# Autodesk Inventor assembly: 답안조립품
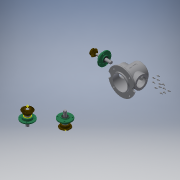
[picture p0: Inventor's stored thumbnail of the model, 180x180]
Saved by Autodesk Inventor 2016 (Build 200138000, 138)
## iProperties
Created: 2018-04
Part Number: 답안조립품
Material: 일반
Document SubType Name: Assembly
Designer: 605-06
Author: 605-06
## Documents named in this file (16)
- C:\Users\605-06\Desktop\480407V1010\답안조립품.iam
- C:\Users\605-06\Desktop\480407V1010\메인 베벨기어.ipt
- C:\Users\605-06\Desktop\480407V1010\메인 축.ipt
- 메인 축.ipt
- C:\Users\605-06\Desktop\480407V1010\베어링 6203.ipt
- C:\Users\605-06\Desktop\480407V1010\본체.ipt
- C:\Users\605-06\Desktop\480407V1010\볼트 M4.ipt
- 볼트 M4.ipt
- C:\Users\605-06\Desktop\480407V1010\서브 베벨기어.ipt
- C:\Users\605-06\Desktop\480407V1010\서브 축.ipt
- 서브 축.ipt
- C:\Users\605-06\Desktop\480407V1010\오일 실.ipt
- 오일 실.ipt
- C:\Users\605-06\Desktop\480407V1010\커버.ipt
- C:\Users\605-06\Desktop\480407V1010\키 4x4.ipt
- C:\Users\605-06\Desktop\480407V1010\키 5x5.ipt
